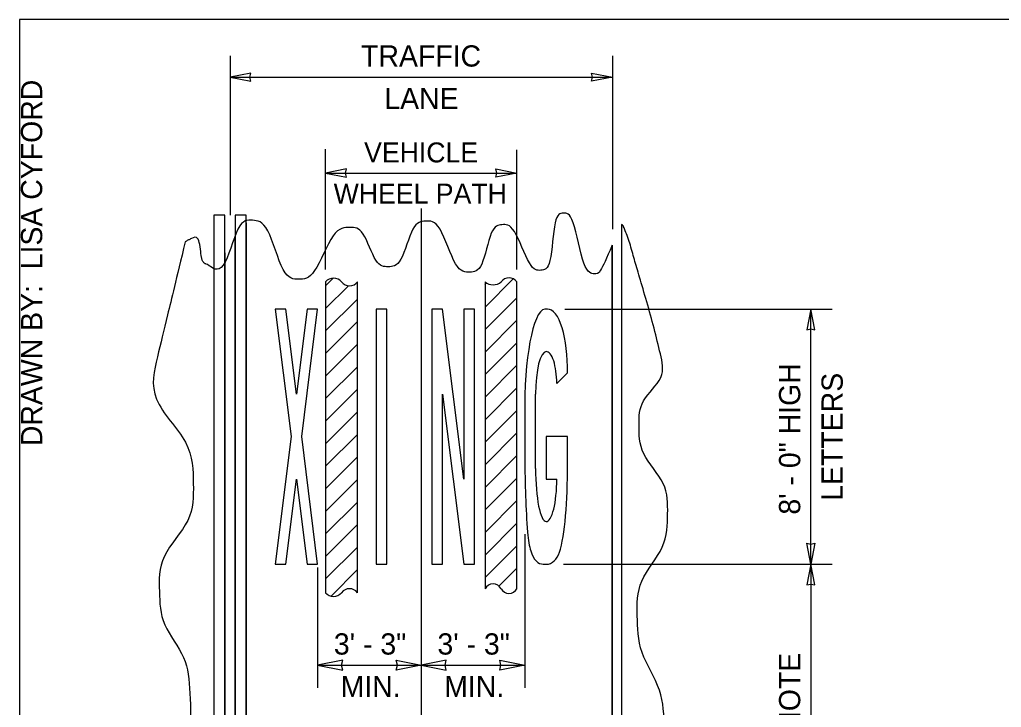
# Model space of a CAD drawing. Extents: x 99862 to 103151, y 100000 to 105076.
# Drawn here: x 99862 to 100601, y 101558 to 102076 of the extents above; entities that cross this region are included whole.
import ezdxf

# ---------------------------------------------------------------- set-up
doc = ezdxf.new("R2010")
doc.units = 0
for name, color, linetype in [('Level 1', 7, 'Continuous'), ('Level 15', 7, 'Continuous'), ('Level 2', 7, 'Continuous'), ('Level 20', 7, 'Continuous'), ('Level 6', 7, 'Continuous'), ('Level 62', 7, 'Continuous'), ('Level 7', 7, 'Continuous'), ('Level 8', 7, 'Continuous')]:
    doc.layers.add(name, color=color, linetype=linetype)

msp = doc.modelspace()

# ---------------------------------------------------------------- linework, layer by layer
at = {"layer": 'Level 1'}
msp.add_lwpolyline([(99862, 99999.5), (103151, 99999.5), (103151, 102075.5), (99862, 102075.5)], close=True, dxfattribs=at)
at = {"layer": 'Level 15'}
for p, q in [((100020.42, 102048.36), (100020.42, 101928.36)), ((100308.42, 102048.36), (100308.42, 101917.83)), ((100020.42, 102032.16), (100308.42, 102032.16)), ((100092.42, 101887.46), (100092.42, 101978.06)), ((100236.42, 101887.46), (100236.42, 101977.56)), ((100092.42, 101960.06), (100236.42, 101960.06)), ((100164.42, 101933.42), (100164.42, 101547.12)), ((100272.66, 101857.67), (100473.85, 101857.67)), ((100457.82, 101665.67), (100457.82, 101857.67)), ((100242.42, 101688.16), (100242.42, 101572.56)), ((100271.66, 101665.67), (100473.82, 101665.67)), ((100457.82, 101665.67), (100457.82, 101425.67)), ((100086.42, 101663.16), (100086.42, 101572.56)), ((100086.42, 101589.56), (100164.42, 101589.56)), ((100164.42, 101589.56), (100242.42, 101589.56))]:
    msp.add_line(p, q, dxfattribs=at)
for points in [[(100020.42, 102032.16), (100036.14, 102029.08), (100035.42, 102032.16), (100036.14, 102035.24)], [(100308.42, 102032.16), (100292.69, 102029.08), (100293.42, 102032.16), (100292.69, 102035.24)], [(100092.42, 101960.06), (100108.14, 101956.98), (100107.42, 101960.06), (100108.14, 101963.14)], [(100236.42, 101960.06), (100220.69, 101956.98), (100221.42, 101960.06), (100220.69, 101963.14)], [(100457.82, 101857.67), (100454.74, 101841.95), (100457.82, 101842.68), (100460.91, 101841.95)], [(100457.82, 101665.67), (100454.74, 101681.4), (100457.82, 101680.67), (100460.91, 101681.4)], [(100457.82, 101665.67), (100454.74, 101649.95), (100457.82, 101650.68), (100460.91, 101649.95)], [(100086.42, 101589.56), (100105.29, 101585.86), (100104.42, 101589.56), (100105.29, 101593.26)], [(100164.42, 101589.56), (100145.55, 101585.86), (100146.42, 101589.56), (100145.55, 101593.26)], [(100164.42, 101589.56), (100183.29, 101585.86), (100182.42, 101589.56), (100183.29, 101593.26)], [(100242.42, 101589.56), (100223.55, 101585.86), (100224.42, 101589.56), (100223.55, 101593.26)]]:
    msp.add_lwpolyline(points, close=True, dxfattribs=at)
at = {"layer": 'Level 2'}
for points in [[(100016.64, 101928.36), (100008.2, 101928.36)], [(100008.2, 101928.36), (100008.2, 101095.2)], [(100016.64, 101095.2), (100016.64, 101928.36)], [(100032.64, 101928.36), (100024.2, 101928.36)], [(100024.2, 101928.36), (100024.2, 101095.2)], [(100032.64, 101095.2), (100032.64, 101928.36)]]:
    msp.add_lwpolyline(points, dxfattribs=at)
at = {"layer": 'Level 6'}
for p, q in [((100092.44, 101875.08), (100098.14, 101880.79)), ((100212.44, 101859.18), (100234, 101880.75)), ((100092.44, 101858.11), (100109.58, 101875.25)), ((100212.44, 101876.16), (100213.37, 101877.09)), ((100092.44, 101841.14), (100116.44, 101865.14)), ((100212.44, 101842.21), (100236.44, 101866.21)), ((100092.44, 101824.17), (100116.44, 101848.17)), ((100212.44, 101825.24), (100236.44, 101849.24)), ((100092.44, 101807.2), (100116.44, 101831.2)), ((100212.44, 101808.27), (100236.44, 101832.27)), ((100092.44, 101790.23), (100116.44, 101814.23)), ((100212.44, 101791.3), (100236.44, 101815.3)), ((100092.44, 101773.26), (100116.44, 101797.26)), ((100212.44, 101774.33), (100236.44, 101798.33)), ((100092.44, 101756.29), (100116.44, 101780.29)), ((100212.44, 101757.36), (100236.44, 101781.36)), ((100092.44, 101739.32), (100116.44, 101763.32)), ((100212.44, 101740.39), (100236.44, 101764.39)), ((100092.44, 101722.35), (100116.44, 101746.35)), ((100212.44, 101723.42), (100236.44, 101747.42)), ((100212.44, 101706.45), (100236.44, 101730.45)), ((100092.44, 101705.38), (100116.44, 101729.38)), ((100092.44, 101688.41), (100116.44, 101712.41)), ((100212.44, 101689.48), (100236.44, 101713.48)), ((100092.44, 101671.43), (100116.44, 101695.43)), ((100212.44, 101672.51), (100236.44, 101696.51)), ((100092.44, 101654.46), (100116.44, 101678.46)), ((100212.44, 101655.54), (100236.44, 101679.54)), ((100096.58, 101641.64), (100116.44, 101661.49)), ((100222.89, 101649.02), (100236.44, 101662.57)), ((100116.28, 101644.36), (100116.44, 101644.52))]:
    msp.add_line(p, q, dxfattribs=at)
for points in [[(100032.74, 101131.76), (100032.74, 101922.58)], [(100315.32, 101921.37), (100315.32, 101121.08)], [(100024.2, 101110.6), (100024.2, 101910.55)], [(100016.74, 101113.29), (100016.74, 101899.91)], [(100308.2, 101905.73), (100308.2, 101136.59)], [(100008.16, 101890.99), (100008.16, 101128.7)], [(100092.44, 101878.16), (100092.44, 101644.16)], [(100116.44, 101644.16), (100116.44, 101878.16)], [(100212.44, 101878.16), (100212.44, 101647.16)], [(100236.44, 101647.16), (100236.44, 101878.16)]]:
    msp.add_lwpolyline(points, dxfattribs=at)
for centre, radius, start, end in [((100098.44, 101872.99), 7.92, 40.75287, 139.24713), ((100110.44, 101882.66), 7.5, 216.8699, 323.1301), ((100218.54, 101885.31), 9.4, 229.51347, 310.48653), ((100230.54, 101873.87), 7.29, 36.05144, 143.94856), ((100218.48, 101643.83), 6.9, 28.88658, 151.11342), ((100098.39, 101649.08), 7.72, 219.50691, 320.49309), ((100110.39, 101639.63), 7.55, 36.89097, 143.10903), ((100230.48, 101650.48), 6.82, 209.09347, 330.90653)]:
    msp.add_arc(centre, radius, start, end, dxfattribs=at)
at = {"layer": 'Level 7'}
msp.add_line((100308.2, 101137.19), (100308.2, 101905.73), dxfattribs=at)
msp.add_lwpolyline([(100315.32, 101921.37), (100315.32, 101121.36)], dxfattribs=at)
for points in [[(100308.2, 101905.73), (100303.65, 101895.46), (100298.91, 101883.98), (100295.44, 101884.14), (100286.85, 101884.55), (100278.79, 101930.32), (100271.23, 101929.88), (100264.47, 101929.48), (100262.34, 101887.29), (100254.41, 101886.83), (100246.68, 101886.39), (100233.9, 101922.07), (100225.16, 101921.13), (100216.84, 101920.24), (100210.39, 101885.82), (100201.28, 101885.49), (100190.43, 101885.09), (100178.42, 101924.38), (100167.46, 101923.82), (100157.96, 101923.34), (100149.29, 101889.55), (100139.41, 101889.52), (100130.28, 101889.5), (100120.67, 101919.02), (100111.16, 101919.12), (100098.34, 101919.24), (100083.58, 101880.03), (100072.15, 101880.11), (100060.45, 101880.19), (100048.83, 101923.67), (100037.18, 101924.5), (100026.41, 101925.26), (100015.65, 101881.49), (100002.61, 101892.2), (100002.09, 101891.21), (100000.36, 101892.78), (99998.67, 101895.35), (99997.27, 101913.83), (99990.61, 101910.37), (99989.32, 101909.7), (99988.03, 101909.03), (99986.74, 101908.35)], [(100342.39, 101140.33), (100343.05, 101193.59), (100343.35, 101221.44), (100343.24, 101249.25), (100343.16, 101267.88), (100334.87, 101286.42), (100333.82, 101304.4), (100332.58, 101325.73), (100353.76, 101346.44), (100343.53, 101367.62), (100354.31, 101395.33), (100330, 101422.93), (100329.79, 101451.02), (100329.55, 101481.13), (100347.62, 101512.17), (100347.27, 101542.48), (100346.95, 101570.84), (100327.58, 101599.24), (100327.1, 101627.23), (100326.65, 101652.93), (100349.64, 101678.47), (100349.96, 101703.9), (100350.25, 101726.34), (100328.36, 101748.7), (100328.44, 101771.15), (100328.5, 101788.6), (100348.8, 101806.09), (100344.58, 101823.61), (100339.87, 101843.2), (100334.33, 101863.07), (100328.44, 101882.8), (100324.79, 101895.04), (100321.7, 101907.15), (100317.01, 101919.12), (100316.51, 101920.39), (100315.94, 101921.11), (100315.32, 101921.37)], [(99986.74, 101908.35), (99979.79, 101879.66), (99972.84, 101850.96), (99965.89, 101822.27), (99958, 101789.7), (99992.55, 101757.43), (99992.79, 101725.42), (99992.99, 101698.46), (99966.44, 101671.63), (99967.23, 101644.71), (99967.96, 101620.09), (99988.64, 101595.42), (99990.1, 101570.73), (99992.4, 101532.03), (99967.11, 101489.92), (99969.92, 101451.02), (99971.75, 101425.72), (99998.67, 101403.5), (100000.86, 101378.38), (100003.66, 101346.21), (99973.73, 101312.37), (99976.65, 101280.19), (99978.34, 101261.5), (99994.95, 101243.68), (99992.42, 101225.04), (99997.62, 101202.75), (99988.02, 101178.88), (99982.85, 101153.77)]]:
    msp.add_open_spline(points, degree=3, dxfattribs=at)
at = {"layer": 'Level 8'}
for p, q in [((100259.48, 101857.67), (100257.36, 101857.67)), ((100266.48, 101801.67), (100274.48, 101809.67)), ((100250.48, 101737.67), (100250.48, 101793.67)), ((100242.48, 101777.67), (100242.48, 101745.67)), ((100274.49, 101761.66), (100258.49, 101761.66)), ((100258.49, 101761.66), (100258.49, 101729.66)), ((100274.49, 101745.66), (100274.49, 101761.66)), ((100258.49, 101729.66), (100266.49, 101729.66)), ((100256.32, 101665.67), (100258.49, 101665.67)), ((100258.49, 101665.66), (100260.27, 101665.67))]:
    msp.add_line(p, q, dxfattribs=at)
for points in [[(100066.42, 101761.66), (100054.42, 101665.66), (100062.42, 101665.66), (100070.42, 101729.66), (100078.42, 101665.66), (100086.42, 101665.66), (100074.42, 101761.66), (100086.42, 101857.66), (100078.42, 101857.66), (100070.42, 101793.66), (100062.42, 101857.66), (100054.42, 101857.66)], [(100130.42, 101665.66), (100138.42, 101665.66), (100138.42, 101857.66), (100130.42, 101857.66)], [(100180.42, 101793.66), (100196.42, 101665.66), (100204.42, 101665.66), (100204.42, 101857.66), (100196.42, 101857.66), (100196.42, 101729.66), (100180.42, 101857.66), (100172.42, 101857.66), (100172.42, 101665.66), (100180.42, 101665.66)]]:
    msp.add_lwpolyline(points, close=True, dxfattribs=at)
for points in [[(100054.42, 101857.66), (100066.42, 101761.66), (100054.42, 101665.66), (100062.42, 101665.66), (100070.42, 101729.66), (100078.42, 101665.66), (100086.42, 101665.66), (100074.42, 101761.66), (100086.42, 101857.66), (100078.42, 101857.66), (100070.42, 101793.66), (100062.42, 101857.66), (100054.42, 101857.66)], [(100130.42, 101857.66), (100130.42, 101665.66), (100138.42, 101665.66), (100138.42, 101857.66), (100130.42, 101857.66)], [(100180.42, 101665.66), (100180.42, 101793.66), (100196.42, 101665.66), (100204.42, 101665.66), (100204.42, 101857.66), (100196.42, 101857.66), (100196.42, 101729.66), (100180.42, 101857.66), (100172.42, 101857.66), (100172.42, 101665.66), (100180.42, 101665.66)], [(100172.42, 101665.66), (100180.42, 101665.66), (100180.42, 101793.66), (100196.42, 101665.66), (100204.42, 101665.66), (100204.42, 101857.66), (100196.42, 101857.66), (100196.42, 101729.66), (100180.42, 101857.66), (100172.42, 101857.66), (100172.42, 101665.66)], [(100259.48, 101857.67), (100257.36, 101857.67)], [(100266.48, 101801.67), (100274.48, 101809.67)], [(100250.48, 101737.67), (100250.48, 101793.67)], [(100242.48, 101777.67), (100242.48, 101745.67)], [(100274.49, 101745.66), (100274.49, 101761.66), (100258.49, 101761.66), (100258.49, 101729.66), (100266.49, 101729.66)], [(100256.32, 101665.67), (100258.49, 101665.66), (100260.27, 101665.67)]]:
    msp.add_lwpolyline(points, dxfattribs=at)
for centre, major_axis, ratio, start_param, end_param in [((100258.75, 101780.89), (0.74, -76.85), 0.212259, 3.181472, 4.752268), ((100258.75, 101780.89), (0.74, -76.85), 0.212259, 3.181472, 4.752268), ((100258.45, 101809.93), (-1.06, -47.74), 0.33574, 1.572843, 3.14364), ((100258.45, 101809.93), (-1.06, -47.74), 0.33574, 1.572843, 3.14364), ((100258.48, 101793.67), (0, -32), 0.25, 3.141593, 4.712389), ((100258.48, 101793.67), (0, -32), 0.25, 3.141593, 4.712389), ((100258.48, 101801.67), (0, -24), 0.333333, 1.570796, 3.141593), ((100258.48, 101801.67), (0, -24), 0.333333, 1.570796, 3.141593), ((100284.67, 101783.68), (-9.37, -188.97), 0.217682, 4.925669, 5.24381), ((100284.67, 101783.68), (-9.37, -188.97), 0.217682, 4.925669, 5.24381), ((100261.51, 101744.43), (1.17, -79.46), 0.163572, 0.554902, 1.583899), ((100261.51, 101744.43), (1.17, -79.46), 0.163572, 0.554902, 1.583899), ((100258.48, 101737.67), (0, -40), 0.2, 4.712389, 6.283185), ((100258.48, 101737.67), (0, -40), 0.2, 4.712389, 6.283185), ((100258.48, 101729.66), (0, -31.99), 0.250446, 6.283185, 7.853982), ((100258.48, 101729.66), (0, -31.99), 0.250446, 6.283185, 7.853982), ((100253.87, 101713.71), (-3.02, -43.02), 0.217694, 5.320592, 5.812457), ((100253.87, 101713.71), (-3.02, -43.02), 0.217694, 5.320592, 5.812457), ((100275.23, 101763.02), (-20.56, -97.22), 0.245192, 5.877502, 6.350549), ((100275.23, 101763.02), (-20.56, -97.22), 0.245192, 5.877502, 6.350549), ((100133.41, 101973.61), (127.98, -307.55), 0.169539, 6.262162, 6.489093), ((100133.41, 101973.61), (127.98, -307.55), 0.169539, 6.262162, 6.489093)]:
    msp.add_ellipse(centre, major_axis=major_axis, ratio=ratio, start_param=start_param, end_param=end_param, dxfattribs=at)

# ---------------------------------------------------------------- texts
at = {"layer": 'Level 20'}
for s, height, rotation, p in [('TRAFFIC', 16, 360, (100119.15, 102040.16)), ('LANE', 16, 360, (100136.64, 102008.16)), ('VEHICLE', 15, 360, (100121.4, 101968.06)), ('WHEEL PATH', 15, 360, (100098.48, 101937.06)), ('8\' - 0" HIGH', 16, 90, (100449.82, 101702.92)), ('LETTERS', 16, 90, (100481.82, 101713.37)), ('3\' - 3"', 16, 360, (100098.63, 101597.56)), ('3\' - 3"', 16, 360, (100176.63, 101597.56)), ('SEE NOTE', 16, 90, (100449.82, 101490.74)), ('MIN.', 16, 360, (100103.7, 101565.56)), ('MIN.', 16, 360, (100181.7, 101565.56))]:
    msp.add_text(s, height=height, rotation=rotation, dxfattribs=at).set_placement(p)
at = {"layer": 'Level 62'}
msp.add_text('DRAWN BY:  LISA CYFORD', height=16, rotation=90, dxfattribs=at).set_placement((99879, 101754.47))

doc.saveas('drawing.dxf')
